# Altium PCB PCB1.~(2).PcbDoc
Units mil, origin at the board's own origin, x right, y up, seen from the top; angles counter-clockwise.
Board outline 1968 x 1968 mil, 4 copper layers (Top Layer, Internal Plane 1, Internal Plane 2, Bottom Layer), stack 18.2 mil thick; 11 components, 12 nets, 36 pads, 0 vias.
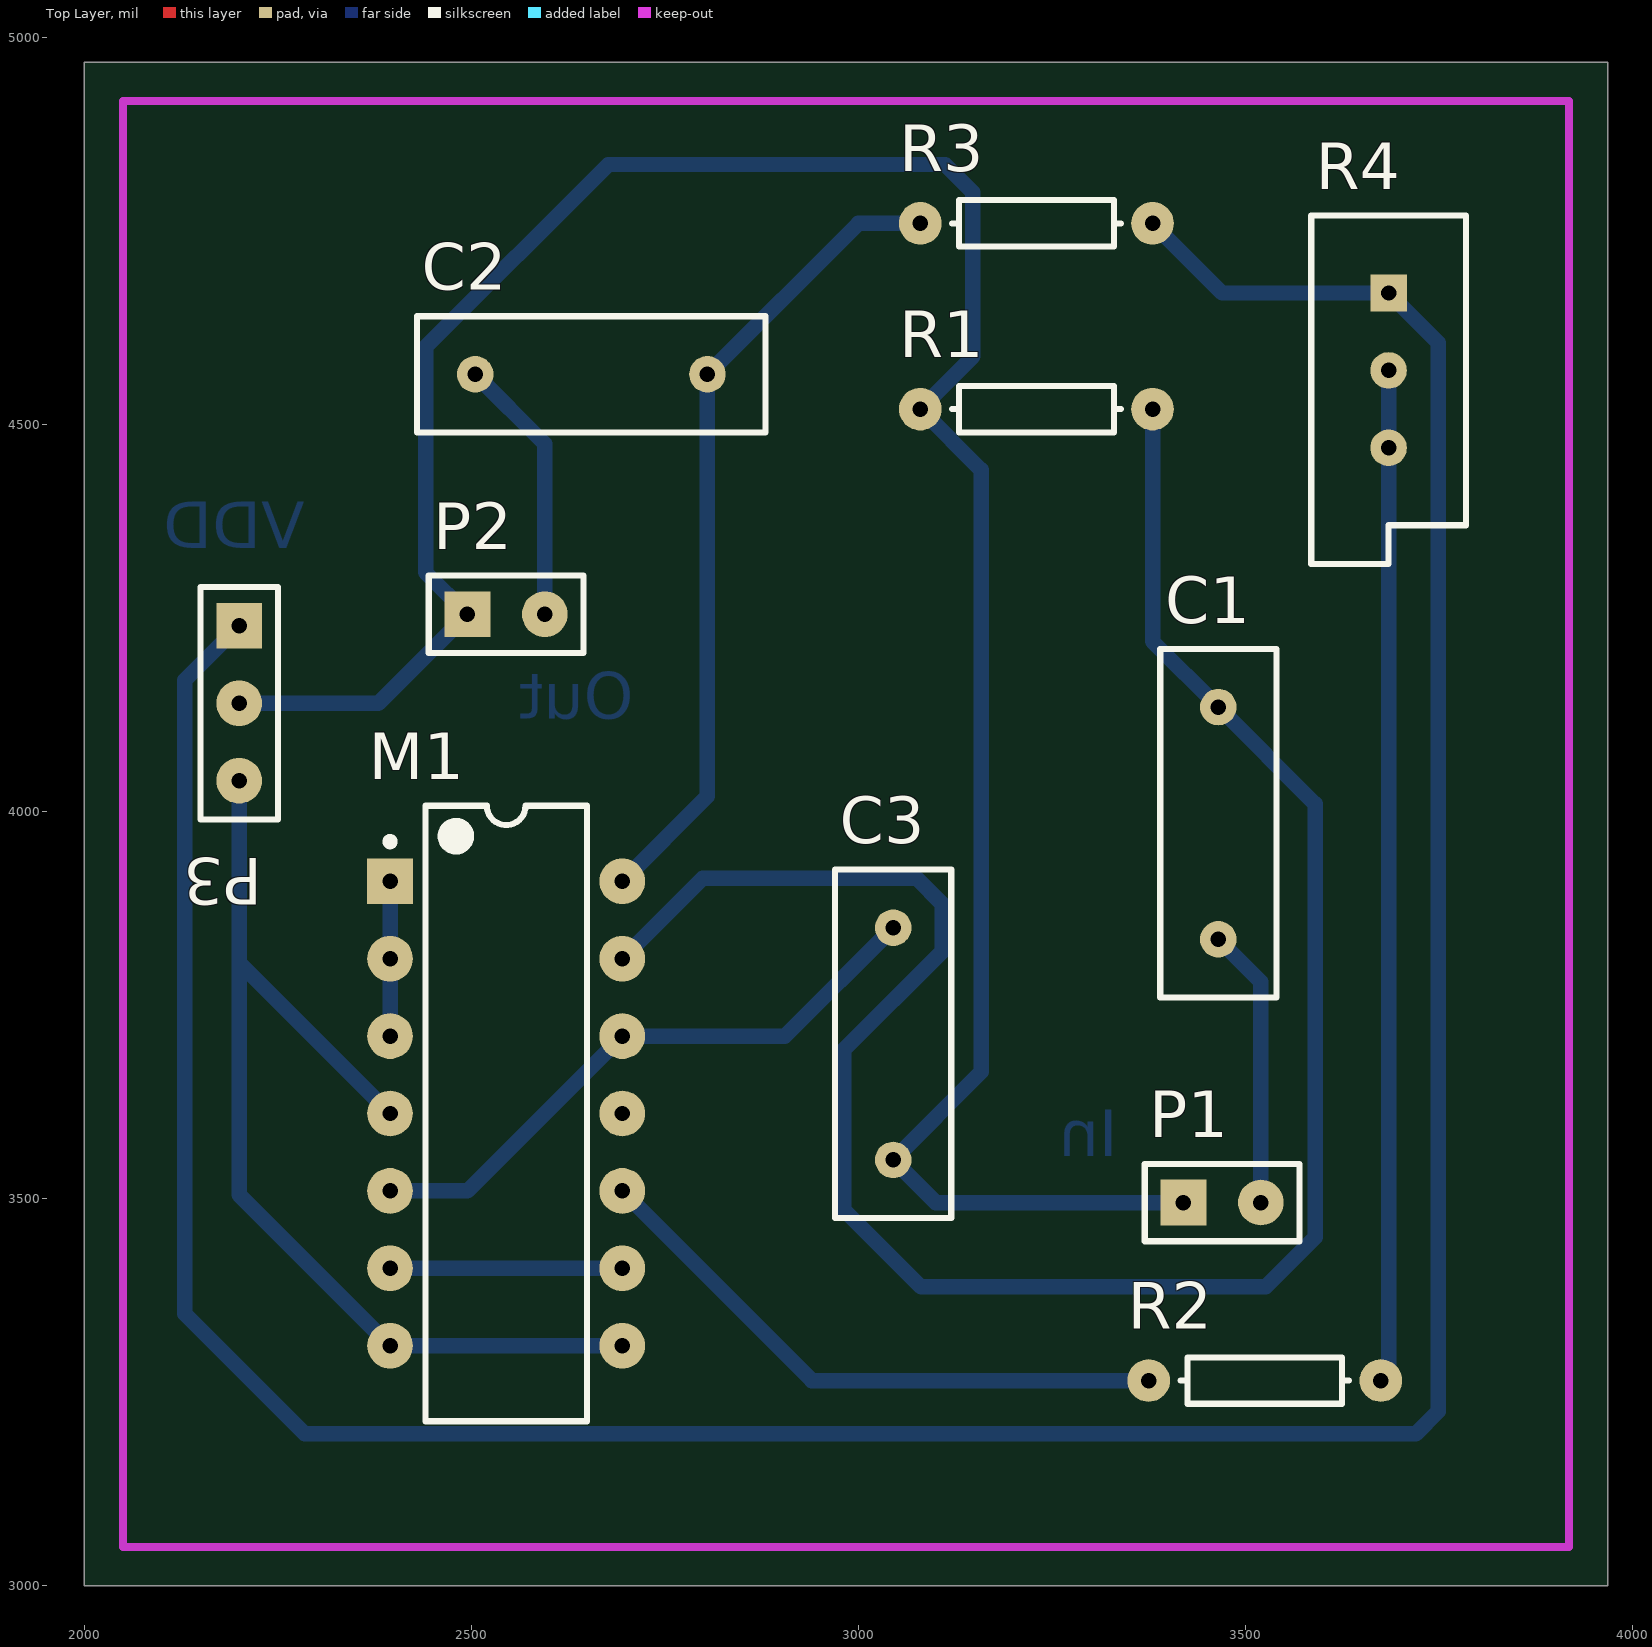
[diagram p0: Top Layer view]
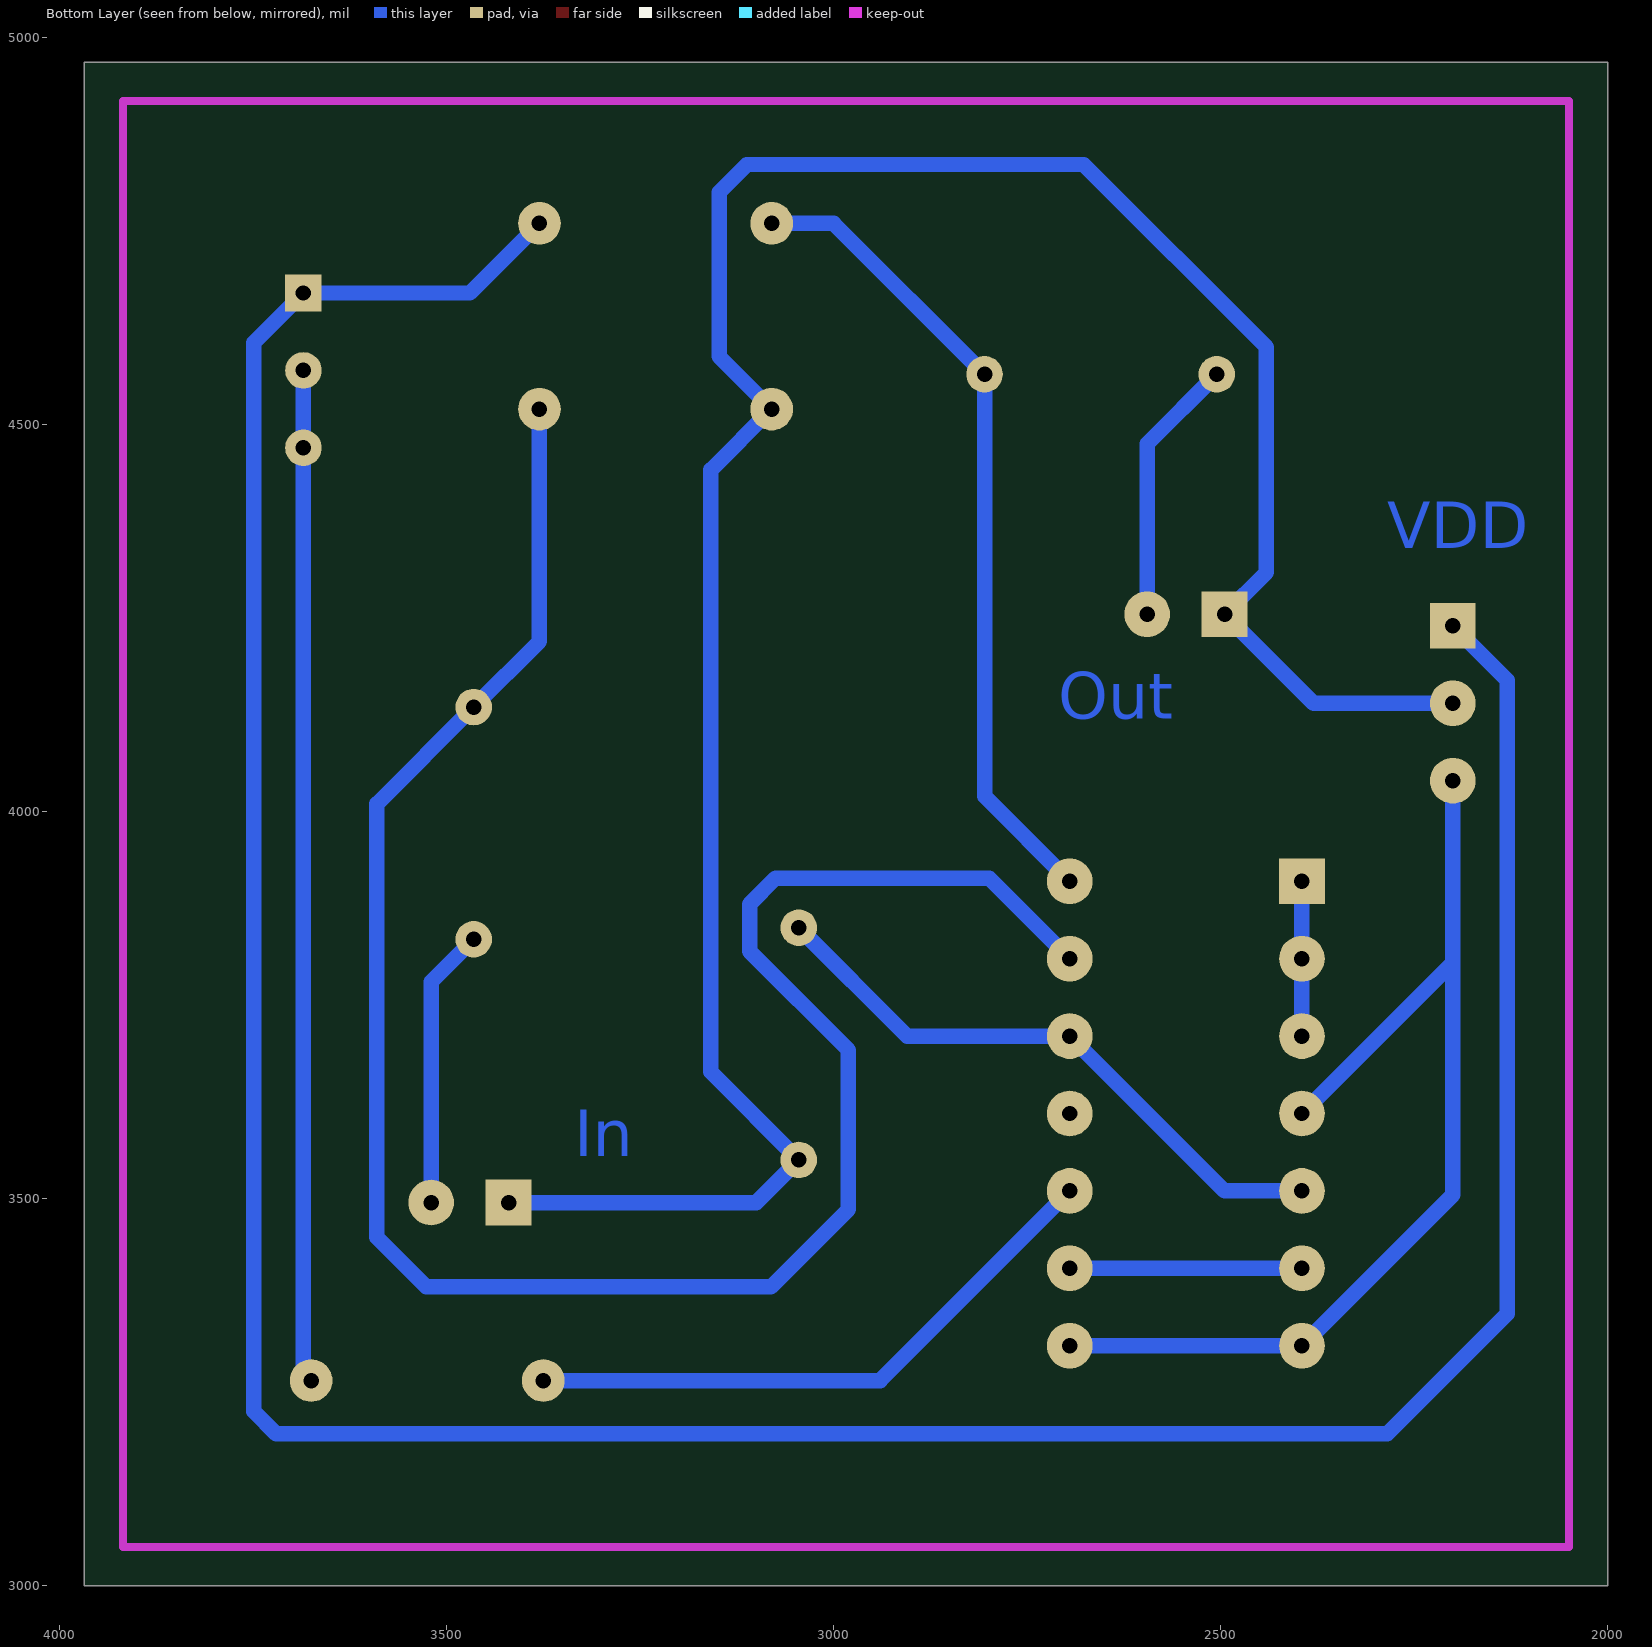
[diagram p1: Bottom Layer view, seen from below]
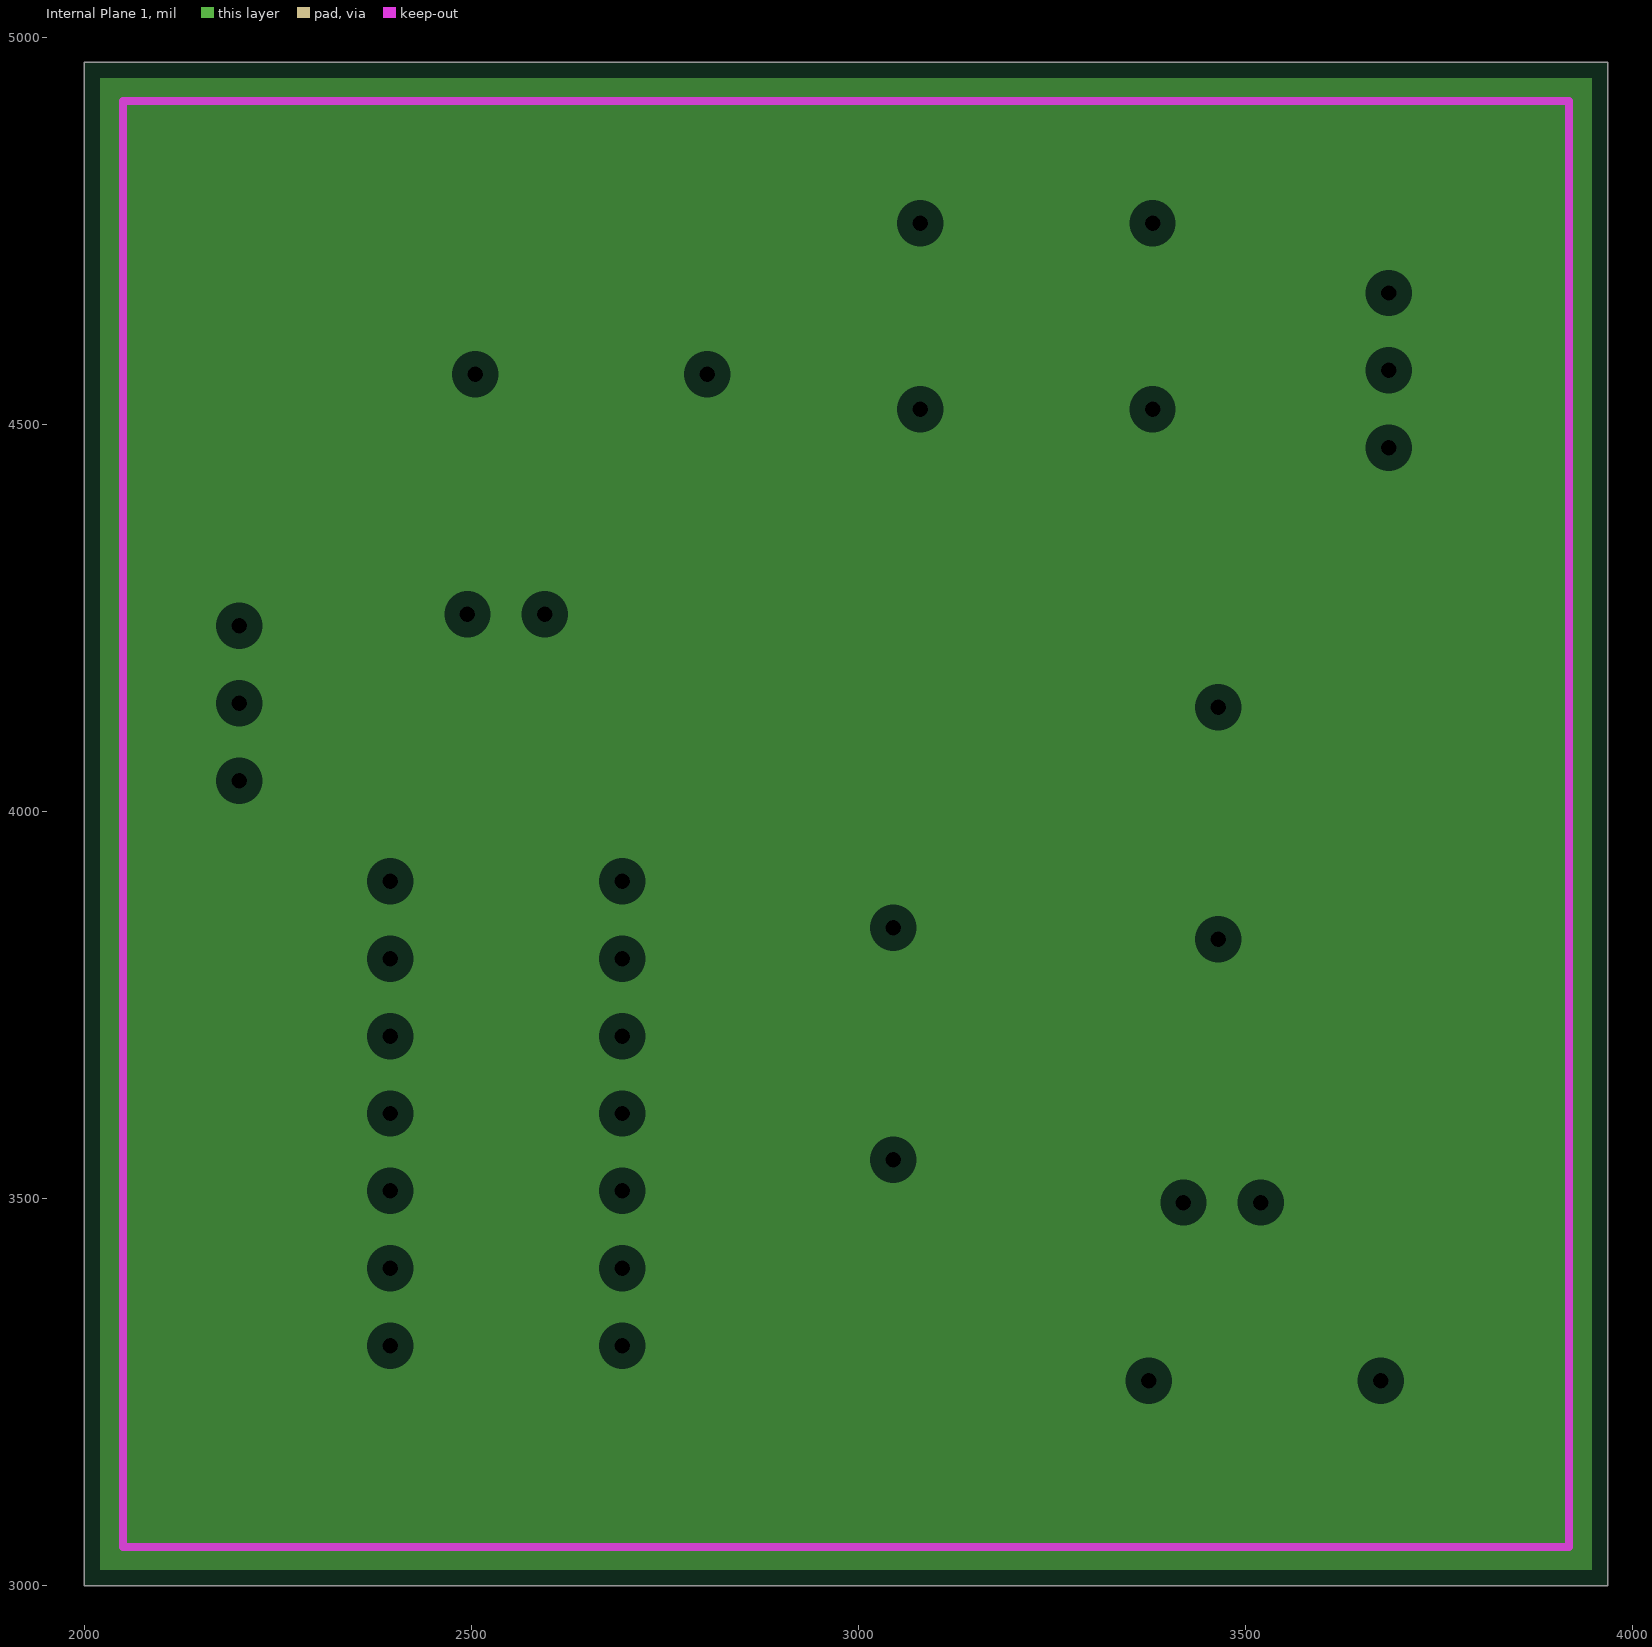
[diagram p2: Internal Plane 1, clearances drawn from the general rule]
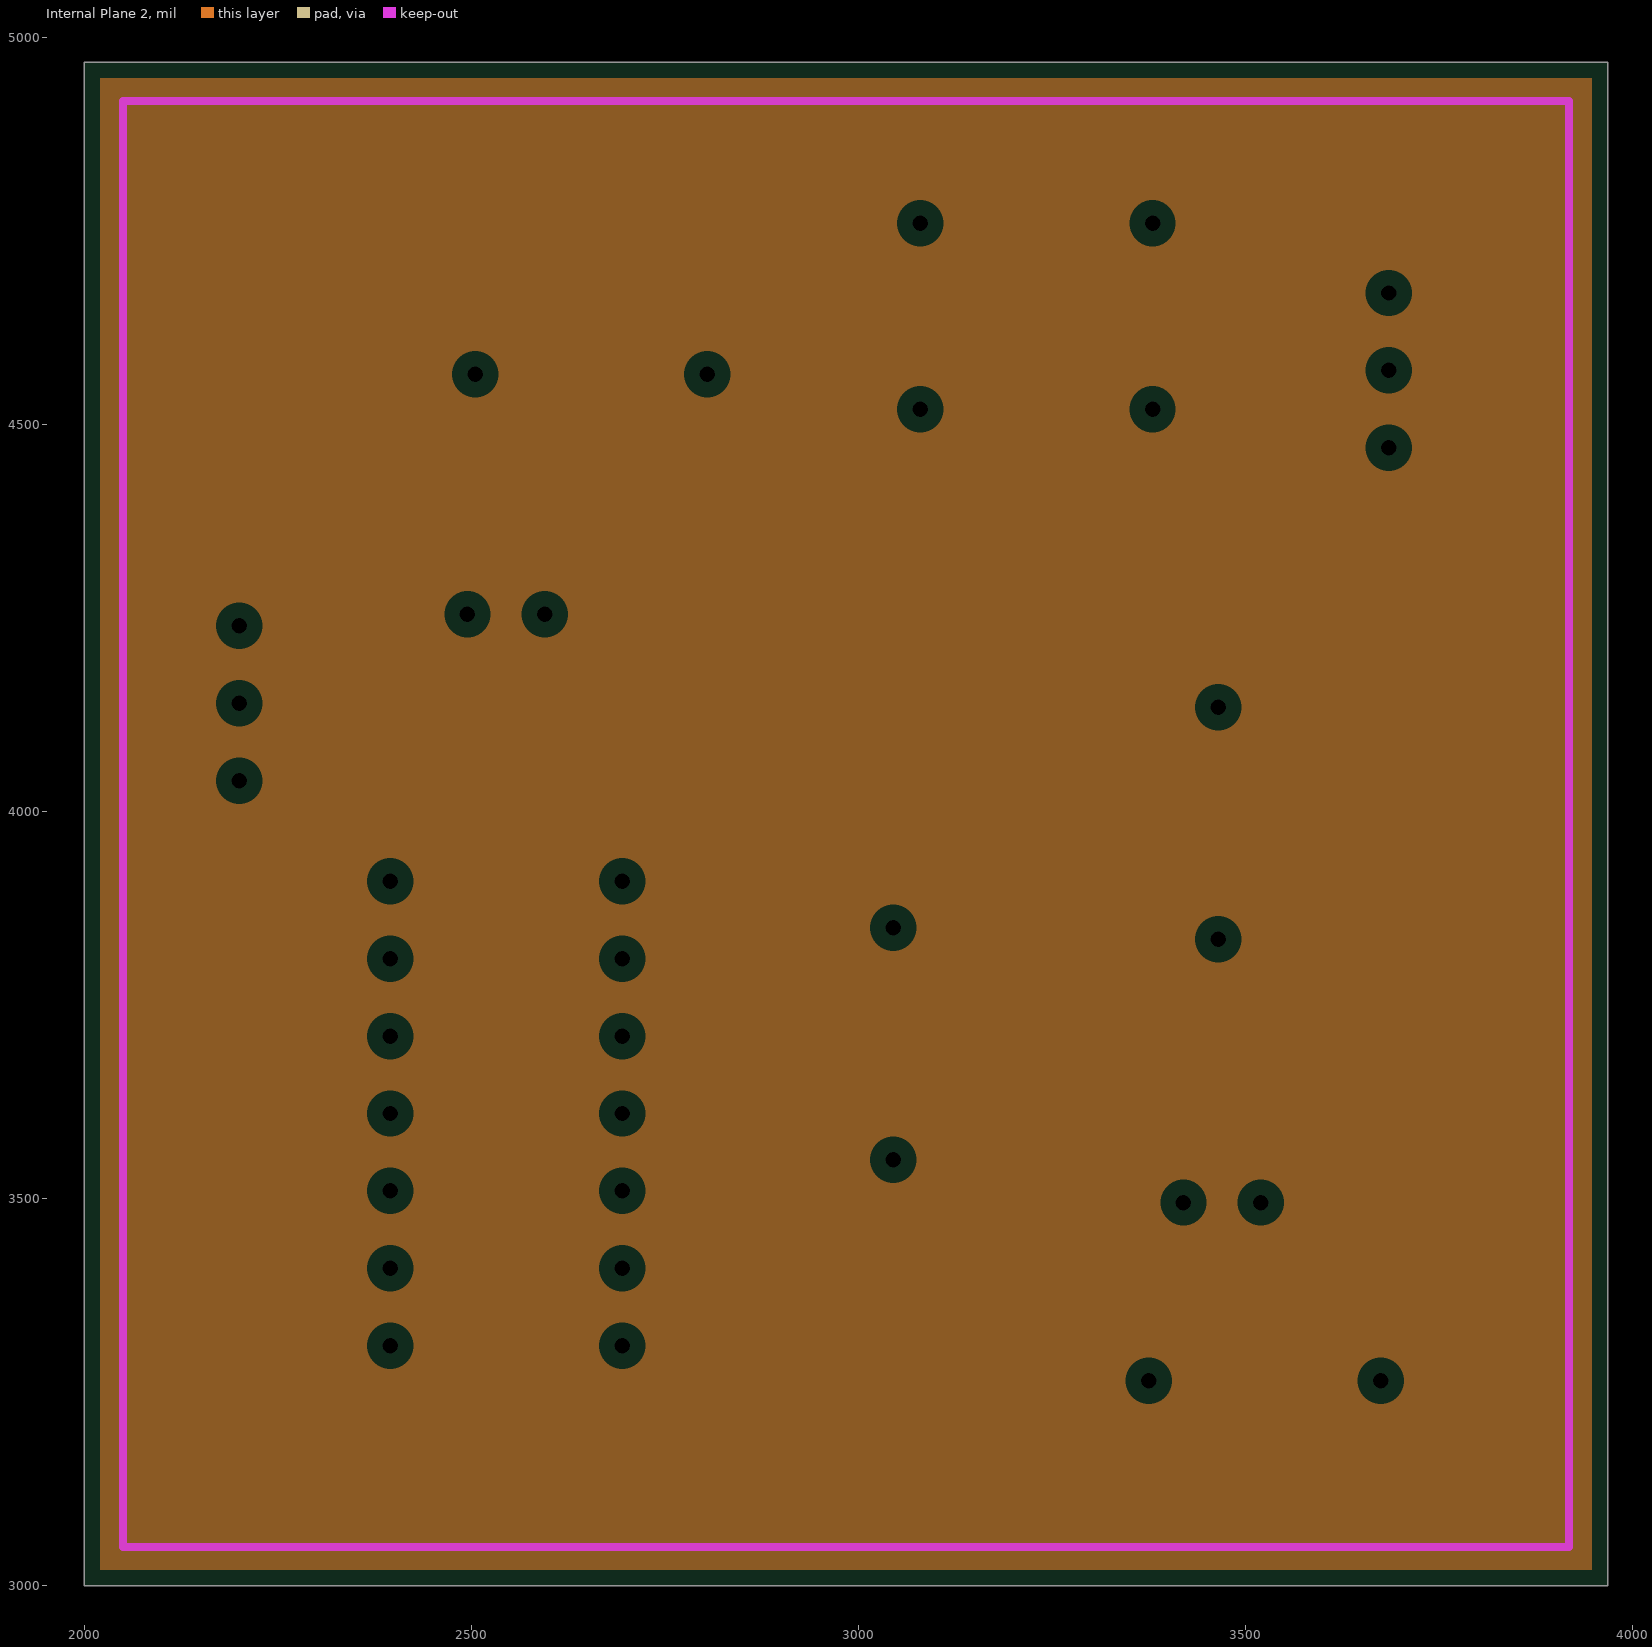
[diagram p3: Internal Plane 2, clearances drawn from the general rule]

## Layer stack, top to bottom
Top Solder: solder mask 0.4, Solder Resist, Dk 3.5
Top Layer: signal copper 1.4
Internal Plane 1: plane copper 1.4
Internal Plane 2: plane copper 1.4
Dielectric 1: dielectric 12.6, FR-4, Dk 4.8
Bottom Layer: signal copper 1.4
Bottom Solder: solder mask 0.4, Solder Resist, Dk 3.5

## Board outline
2000,3000 3968,3000 3968,4968 2000,4968

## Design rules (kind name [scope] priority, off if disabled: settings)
Clearance [All] p1: gap=30
PlaneClearance [All] p1: clearance=20
PlaneConnect [All] p1: planeconnectstyle=Relief reliefexpansion=20 reliefentries=4 reliefconductorwidth=10 reliefairgap=10
PolygonConnect [All] p1: connectstyle=Relief reliefconductorwidth=10 reliefentries=4 polygonreliefangle="90 Angle" airgapwidth=10
RoutingVias [All] p1: holewidth=32 width=62 viastyle="Through Hole" minholewidth=28 minwidth=50 maxholewidth=28 maxwidth=50
SolderMaskExpansion [All] p1: expansion=4
Width [All] p1: maxlimit=20 minlimit=20 preferedwidth=20
28 further rules are at their usual default settings.

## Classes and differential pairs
component class Sheet1: C1 C2 C3 P1 P2 P3 R1 R2 R3 R4

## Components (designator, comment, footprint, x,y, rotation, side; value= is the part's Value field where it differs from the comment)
C1 "Cap" RAD-0.3 3465,3985 r90 top
C2 "Cap" RAD-0.3 2655,4565 r180 top
C3 "Cap" RAD-0.3 3045,3700 r270 top
M1 "ALD1106" DIP-14 2545,3610 r0 top
P1 "Header 2" HDR1X2 3420,3495 r0 top
P2 "Header 2" HDR1X2 2495,4255 r0 top
P3 "Header 3" HDR1X3 2200,4240 r270 top
R1 "Res1" AXIAL-0.3 3230,4520 r0 top
R2 "Res1" AXIAL-0.3 3525,3265 r0 top
R3 "Res1" AXIAL-0.3 3230,4760 r0 top
R4 "RPot" VR5 3685,4570 r270 top

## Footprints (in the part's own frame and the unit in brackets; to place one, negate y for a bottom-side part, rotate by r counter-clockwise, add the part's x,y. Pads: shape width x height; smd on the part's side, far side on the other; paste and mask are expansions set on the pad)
AXIAL-0.3 [mm] "Axial Device, Thru-Hole; 2 Leads; 0.3 in Pin Spacing"
  round 1.4 hole 0.508: 1(-3.81,0) 2(3.81,0)
  silkscreen extent -2.77,-0.76 2.77,0.76
DIP-14 [mm] "DIP, 14-Pin, Row Spacing 7.62 mm, Pitch 2.54 mm"
  rect 1.5x1.5 hole 0.508: 1(-3.81,7.62)
  round 1.5 hole 0.508: 2(-3.81,5.08) 3(-3.81,2.54) 4(-3.81,0) 5(-3.81,-2.54) 6(-3.81,-5.08) 7(-3.81,-7.62) 8(3.81,-7.62) 9(3.81,-5.08) 10(3.81,-2.54) 11(3.81,0) 12(3.81,2.54) 13(3.81,5.08) 14(3.81,7.62)
  silkscreen extent -3.93,-10.1 2.65,10.1, body extent -3.6,-10.1 3.6,10.1, height 5.08
HDR1X2 [mm] "Connector; Header; 2 Position"
  rect 1.5x1.5 hole 0.508: 1(0,0)
  round 1.5 hole 0.508: 2(2.54,0)
  silkscreen extent -1.27,-1.27 3.81,1.27
HDR1X3 [mm] "Connector; Header; 3 Position"
  rect 1.5x1.5 hole 0.508: 1(0,0)
  round 1.5 hole 0.508: 2(2.54,0) 3(5.08,0)
  silkscreen extent -1.27,-1.27 6.35,1.27
RAD-0.3 [mm] "Radial Cap, Thru-Hole; 2 Leads; 0.3 in Pin Spacing"
  round 1.2 hole 0.508: 1(-3.81,0) 2(3.81,0)
  silkscreen extent -5.71,-1.91 5.71,1.91
VR5 [mm] "Thru-Hole; 3 Leads"
  rect 1.2x1.2 hole 0.508: 1(-2.54,0)
  round 1.2 hole 0.508: 2(0,0) 3(2.54,0)
  silkscreen extent -5.08,-2.54 6.35,2.54

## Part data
C1 C2 C3: "Capacitor"
M1: "Quad N-channel matched MOSFET array"
P1 P2: "Header, 2-Pin"
P3: "Header, 3-Pin"
R1 R2 R3: "Resistor"
R4: "Potentiometer"

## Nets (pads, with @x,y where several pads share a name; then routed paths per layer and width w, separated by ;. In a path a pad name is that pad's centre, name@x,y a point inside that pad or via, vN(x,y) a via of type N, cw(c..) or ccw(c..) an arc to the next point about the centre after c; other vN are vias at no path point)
GND: C3.2 P1.1 P2.1 P3.2 R1.1 | length 3285.2
  Bottom Layer w20: P3.2 2380,4140 P2.1 2441,4309 2441,4600 2677,4836 3112,4836 3148,4800 3148,4588 R1.1 3158.62,4441.38 3158.62,3663.62 C3.2 3100,3495 P1.1
NetC1_1: C1.1 P1.2 | length 362.8
  Bottom Layer w20: C1.1 3520,3780 P1.2
NetC1_2: C1.2 M1.13 R1.2 | length 2751.8
  Bottom Layer w20: M1.13 2799,3914 3075,3914 3108.62,3880.38 3108.62,3819.62 2981,3692 2981,3486 3081,3386 3526,3386 3590,3450 3590,4010 C1.2 3380,4220 R1.2
NetC2_1: C2.1 M1.14 R3.1 | length 1056.3
  Bottom Layer w20: M1.14 2805,4020 C2.1 3000,4760 R3.1
NetC2_2: C2.2 P2.2 | length 347.3
  Bottom Layer w20: C2.2 2595,4475 P2.2
NetC3_1: C3.1 M1.5 M1.12 | length 790.8
  Bottom Layer w20: M1.5 2495,3510 M1.12 2905,3710 C3.1
NetM1_1: M1.1 M1.2 M1.3 | length 200
  Bottom Layer w20: M1.3 M1.2 M1.1
NetM1_6: M1.6 M1.9 | length 300
  Bottom Layer w20: M1.6 M1.9
NetM1_10: M1.10 R2.1 | length 781.5
  Bottom Layer w20: M1.10 2940,3265 R2.1
NetR2_2: R2.2 R4.2 R4.3 | length 1295
  Bottom Layer w20: R2.2@3685,3275 R4.3 R4.2
VDD: P3.1 R3.2 R4.1 | length 4427
  Bottom Layer w20: P3.1 2130,4170 2130,3351 2285,3196 3720,3196 3749,3225 3749,4606 R4.1 3470,4670 R3.2
VSS: M1.4 M1.7 M1.8 P3.3 | length 1386.5
  Bottom Layer w20: P3.3 2200,3805 ; M1.4 2200,3805 ; M1.8 M1.7 2200,3505 2200,3805
pads on no net: M1.11

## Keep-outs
Keep-Out Layer:
  lines w10: 2050,3050 2050,4918 3918,4918 3918,3050 2050,3050

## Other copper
Bottom Layer:
  text "VDD" at 2285,4340 h60
  text "Out" at 2710,4120 h60
  text "In" at 3335,3555 h60

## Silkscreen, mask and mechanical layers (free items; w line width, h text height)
Drill Drawing:
  text ".LEGEND" at 4168,3200 h60
  text "Drill Drawing." at 4168,3100 h60

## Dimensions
2050,3050 to 2050,4918 on Mechanical 1
2050,3050 to 3918,3050 on Mechanical 1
